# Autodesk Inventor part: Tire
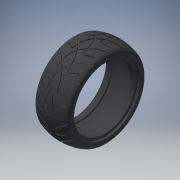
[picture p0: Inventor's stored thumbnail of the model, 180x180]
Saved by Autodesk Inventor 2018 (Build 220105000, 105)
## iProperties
Shininess: 25.0
Length Units: 11272
Angle Units: 11279
Time Units: 11290
Mass Units: 11286
Length Display Precision: 4
Angle Display Precision: 2
Compacted: True
Company: Autodesk
Created: 2000-05
Part Number: Tire
Project: Inventor Samples
User Status: IN PROGRESS
Document SubType Name: Modeling
Designer: Autodesk, Inc.
Density: 0.93 g/cm^3
Material: Rubber
Mass: 9.0169 g
Surface Area: 189.656 cm^2
Volume: 9.69559 cm^3
Appearance: Black
Density: 0.0
Volumn: 0.0
Area: 0.0
PropertySet Name: Model Information
Control State: 0
Master: False
Checked Out: False
Last Check In By: Kevin.s
Last Check In Date: 2002-03-02
Author: Autodesk, Inc.
Revision Number: A
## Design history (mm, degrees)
node "Revolution1" dims "d7" = 90 deg
  sketch "Sketch2"
    geometry: L1 (-10.926, 4.597)-(-14.99, 4.597); L2 (-14.99, 4.597)-(-14.99, 6.629); L3 (-14.99, 6.629)-(-16.768, 6.629); L4 (-16.768, 6.629)-(-16.768, 10.893); L5 (-19.353, -19.342)-(12.36, -19.342) reference; L6 (9.775, 10.893)-(9.775, 6.629); L7 (9.775, 6.629)-(7.997, 6.629); L8 (7.997, 6.629)-(7.997, 4.597); L9 (7.997, 4.597)-(3.933, 4.597); L10 (-10.926, 5.867)-(-13.72, 5.867); L11 (-13.72, 5.867)-(-13.72, 7.899); L12 (-13.72, 7.899)-(-15.498, 7.899); L13 (-15.498, 7.899)-(-15.498, 10.052); L14 (8.505, 10.052)-(8.505, 7.899); L15 (8.505, 7.899)-(6.727, 7.899); L16 (6.727, 7.899)-(6.727, 5.867); L17 (6.727, 5.867)-(3.933, 5.867); L18 (-10.926, 4.597)-(-10.926, 5.867); L19 (3.933, 4.597)-(3.933, 5.867); A1 r 33.02 centre (-3.496, -19.342) between (9.775, 10.893) and (-16.768, 10.893); A2 r 31.75 centre (-3.496, -19.342) between (8.505, 10.052) and (-15.498, 10.052)
    constraints: 38 end point, 9 parallel, 7 perpendicular, 4 collinear, 4 equal length, 4 point on circle, 2 centre point, 2 horizontal, 2 midpoint, 1 horizontal alignment, 9 other
    dimensions: "d0" = 47.879 diameter of L1 L5; "d1" = 51.943 diameter of L3 L5; "d2" = 1.778 distance of L2.end L3.end; "d3" = 5.842 distance from line of L4 L1.start; "d4" = 26.543 distance between parallel lines of L6 L4; "d5" = 66.04 dimension on A1 L5; "d6" = 1.27 radial gap between concentric circles of A1 A2
workaxis "Work Axis1"
node "Fillet1" dims "d8" = 3.175
sketch "Sketch7"
  geometry: L1 (-46.46, -19.342)-(23.146, -19.342) reference; A1 r 33.02 centre (-3.496, -19.342) between (7.674, 11.731) and (7.674, -50.415) reference; A2 r 32.266 centre (-3.496, -19.342) between (13.202, 8.266) and (-20.195, 8.266)
  constraints: 2 point on circle, 1 centre point, 1 coincident
feature "RevolutionSrf1" sketch "Sketch7" dims angle "d63" = 90 deg
workplane "Work Plane6"
sketch "Sketch8"
  geometry: L1 (-9.775, -14.127)-(-9.775, -13.038); L2 (-9.775, -28.085)-(-9.775, 28.085) reference; L3 (7.675, 6.132)-(7.941, 8.812); L4 (8.727, 9.228)-(13.347, 6.713); L5 (13.851, 7.638)-(9.231, 10.154); L6 (8.15, 14.674)-(8.152, 14.673); L7 (6.892, 8.916)-(6.626, 6.236); L8 (23.217, 0)-(-21.924, 0) reference; L9 (16.768, 28.085)-(16.768, -28.085) reference; A1 r 23.264 centre (-15.476, 8.428) between (-9.775, -14.127) and (7.685, 6.236); A2 r 22.21 centre (-15.476, 8.428) between (-9.775, -13.038) and (6.626, 6.236); A3 r 0.533 centre (8.472, 8.76) between (8.727, 9.228) and (7.941, 8.812); A4 r 0.527 centre (13.599, 7.175) between (13.347, 6.713) and (13.851, 7.638); A5 r 1.587 centre (8.472, 8.76) between (9.231, 10.154) and (6.892, 8.916)
  constraints: 12 end point, 11 point on circle, 6 tangent, 5 centre point, 3 parallel, 2 concentric, 1 collinear, 1 horizontal alignment
  dimensions: "d72" = 1.0541 radial gap between concentric circles of A1 A2; "d76" = 0.52705 radius of A4 (= 0.5 x d72); "d77" = 14.12735 distance from line of L1.start L8; "d78" = 1.5875 radius of A5; "d79" = 7.1755 distance from line of L8 A4.centre; "d80" = 3.16916 distance from line of L9 A4.centre
extrude "Extrusion1" cut sketch "Sketch8" stored distance "d65" = 25.4; taper "d66" = 0 deg
pattern_circular "Circular Pattern5" dims angle "d70" = 360 deg
workplane "Work Plane7"
mirror "Mirror4"
body "Solid1"
body "Srf1"
other parameters: "d64" = 18.796, "d71" = -13.2715 (= -0.5 x d4)
